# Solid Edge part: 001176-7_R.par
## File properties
Last saved by: morva
Revision: 82
Accuracy: 0.990
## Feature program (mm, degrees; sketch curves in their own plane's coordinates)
body "unnamed Body 1"
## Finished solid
Body 1: solid body, 11 faces, 23 edges, 14 vertices.
  Faces by surface: torus 4, plane 3, cylinder 2, spline 2
  Edges by curve: circle 8, spline 8, curve on surface 4, line 3
Bounding box of the edges (mm; curved faces can reach further): 12.400 x 13.846 x 31.245, from (430.858, 374.4943, 141.0886) to (443.2579, 388.3407, 172.3336).
Cylindrical faces by radius (mm): R3.5 x2
Toroidal faces (ring radius, tube radius in mm): R3 r0.5 x4
Planar faces by outward normal: oblique 3
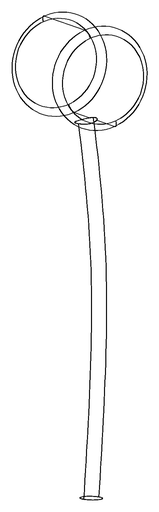
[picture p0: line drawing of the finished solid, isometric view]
